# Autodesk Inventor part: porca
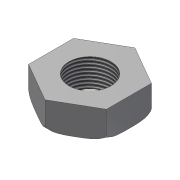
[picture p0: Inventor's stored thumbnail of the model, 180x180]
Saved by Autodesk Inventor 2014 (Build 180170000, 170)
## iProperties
Created: 2012-09
Part Number: porca
Material: Aço
Document SubType Name: Modeling
Designer: TR-06
Density: 1 g/cm^3
Description: Compra em Loja XXXX
Appearance: Steel
Author: TR-06
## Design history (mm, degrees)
sketch "Sketch1" dims "d0" = 80
  geometry: L1 (0, -40)-(-34.641, -20); L2 (-34.641, -20)-(-34.641, 20); L3 (-34.641, 20)-(0, 40); L4 (0, 40)-(34.641, 20); L5 (34.641, 20)-(34.641, -20); L6 (34.641, -20)-(0, -40); 3 further points
  constraints: 12 end point, 2 coincident, 1 vertical alignment, 15 other
extrude "Extrusion1" new body sketch "Sketch1" distance "d1" = 25; taper "d2" = 0 deg
sketch "Sketch2"
  geometry: C1 r 18.75 at (0, 0); 1 further point
  constraints: 1 centre point, 1 coincident
  dimensions: "d3" = 37.5 diameter of C1
extrude "Extrusion2" cut sketch "Sketch2" stored distance "d4" = 25; taper "d5" = 0 deg
workplane "Work Plane1"
sketch "Sketch3"
  geometry: L1 (20, 25)-(0, 25) reference; L2 (0, 25)-(0, 19); L3 (0, 25)-(6, 25); L4 (21.25, 25)-(58.75, 25) reference; L5 (58.75, 0)-(21.25, 0) reference; L6 (40, 25)-(40, 10.452); A1 r 6 centre (6, 19) between (6, 25) and (0, 19)
  constraints: 6 end point, 2 perpendicular, 2 point on circle, 1 centre point, 1 point on line, 1 tangent
  dimensions: "d6" = 6 distance of L1.end L2.end; "d7" = 6 distance of L1.end L3.end
revolve "Revolution1" sketch "Sketch3" stored, may be unused: angle "d8" = 20 deg
thread "Thread1" dims "d9" = 10, "d10" = 0
body "Solid1"
node "Projected Loop1"
